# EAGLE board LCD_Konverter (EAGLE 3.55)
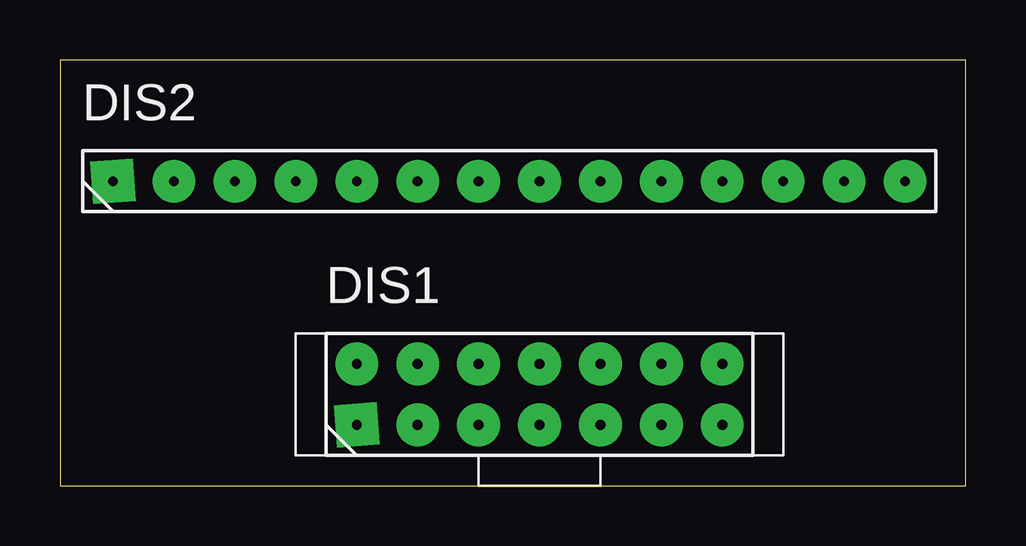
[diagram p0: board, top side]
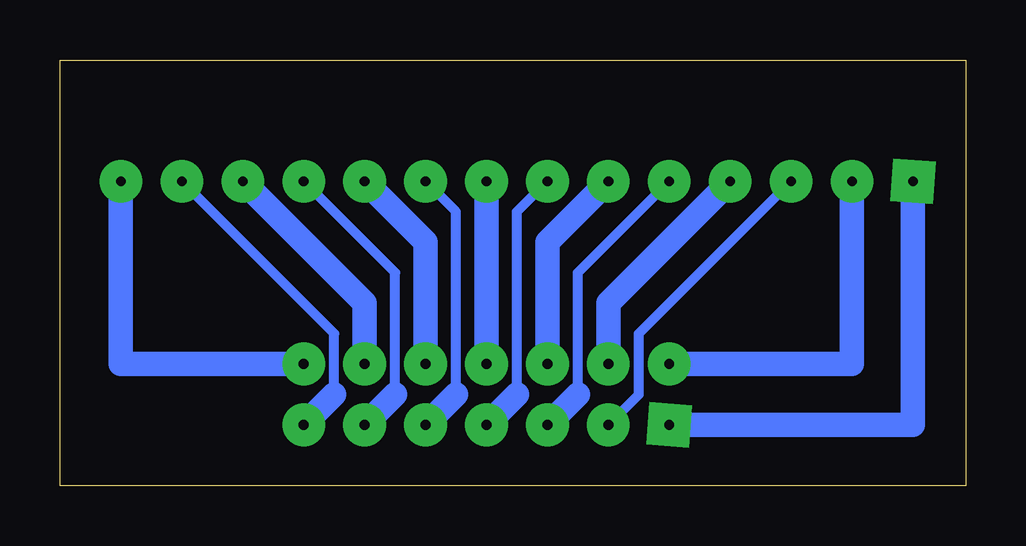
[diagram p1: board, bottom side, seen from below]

Size 37.77 x 17.76 mm. Coordinates in mm from the lower left corner, seen from the top.
Outline: 37.77,0 37.77,17.76 0,17.76 0,0 37.77,0
Copper layers used: Bottom

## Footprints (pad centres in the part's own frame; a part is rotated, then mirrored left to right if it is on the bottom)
7 = drill 0.406 pad 1.778 square:  0,0 | drill 0.406 pad 1.778 round:  2.54,0;  5.08,0;  7.62,0;  10.16,0;  10.16,2.54;  7.62,2.54;  5.08,2.54;  2.54,2.54;  0,2.54;  12.7,0;  12.7,2.54;  15.24,0;  15.24,2.54
14 = drill 0.406 pad 1.778 square:  0,0 | drill 0.406 pad 1.778 round:  5.08,0;  10.16,0;  15.24,0;  20.32,0;  22.86,0;  17.78,0;  12.7,0;  7.62,0;  2.54,0;  25.4,0;  27.94,0;  30.48,0;  33.02,0

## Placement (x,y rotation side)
DIS1  LCD_DOPPEL  [7]  12.37,2.54 0 top
DIS2  LCD_EIREIH  [14]  2.21,12.7 0 top

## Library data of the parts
DIS1 DIS2 = holg_plt

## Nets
N$1: DIS1. DIS2.
N$2: DIS1. DIS2.
N$3: DIS1. DIS2.
N$4: DIS1. DIS2.
N$5: DIS1. DIS2.
N$6: DIS1. DIS2.
N$7: DIS1. DIS2.
N$8: DIS1. DIS2.
N$9: DIS1. DIS2.
N$10: DIS1. DIS2.
N$11: DIS1. DIS2.
N$12: DIS1. DIS2.
N$13: DIS1. DIS2.
N$14: DIS1. DIS2.

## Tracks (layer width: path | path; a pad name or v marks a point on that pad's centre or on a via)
N$1
  Bottom 1.016: 12.37,2.54 2.21,2.54 2.21,12.7
N$2
  Bottom 1.016: 12.37,5.08 4.75,5.08 4.75,12.7
N$3
  Bottom 0.406: 14.91,2.54 13.64,3.81 13.64,6.35 7.29,12.7
N$4
  Bottom 1.016: 14.91,5.08 14.91,7.62 9.83,12.7
N$5
  Bottom 0.406: 16.18,3.81 16.18,8.89 12.37,12.7
  Bottom 1.016: 17.45,2.54 16.18,3.81
N$6
  Bottom 1.016: 17.45,5.08 17.45,10.16 14.91,12.7
N$7
  Bottom 0.406: 18.72,3.81 18.72,11.43 17.45,12.7
  Bottom 1.016: 19.99,2.54 18.72,3.81
N$8
  Bottom 1.016: 19.99,5.08 19.99,12.7
N$9
  Bottom 0.406: 21.26,3.81 21.26,11.43 22.53,12.7
  Bottom 1.016: 22.53,2.54 21.26,3.81
N$10
  Bottom 1.016: 22.53,5.08 22.53,10.16 25.07,12.7
N$11
  Bottom 0.406: 23.8,3.81 23.8,8.89 27.61,12.7
  Bottom 1.016: 25.07,2.54 23.8,3.81
N$12
  Bottom 1.016: 25.07,5.08 25.07,7.62 30.15,12.7
N$13
  Bottom 0.406: 26.34,3.81 26.34,6.35 32.69,12.7
  Bottom 1.016: 27.61,2.54 26.34,3.81
N$14
  Bottom 1.016: DIS1. 35.23,5.08 DIS2.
